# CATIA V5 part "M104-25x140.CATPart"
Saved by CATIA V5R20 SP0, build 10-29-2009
Part number: M104-25x140
Source: Unknown
Bounding box of the stored display mesh (mm): x -12.497 to 12.497, y -12.358 to 12.358, z 0 to 140
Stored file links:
  C:\Users\Utente\Desktop\IO LAVORO\3D X SITO CF\X SITO\M104\M104-25x140.CATPart
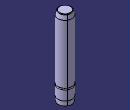
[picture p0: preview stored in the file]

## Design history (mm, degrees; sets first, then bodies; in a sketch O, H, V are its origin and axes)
Body1 (main body)
  Solid1 "PartBody": solid without history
